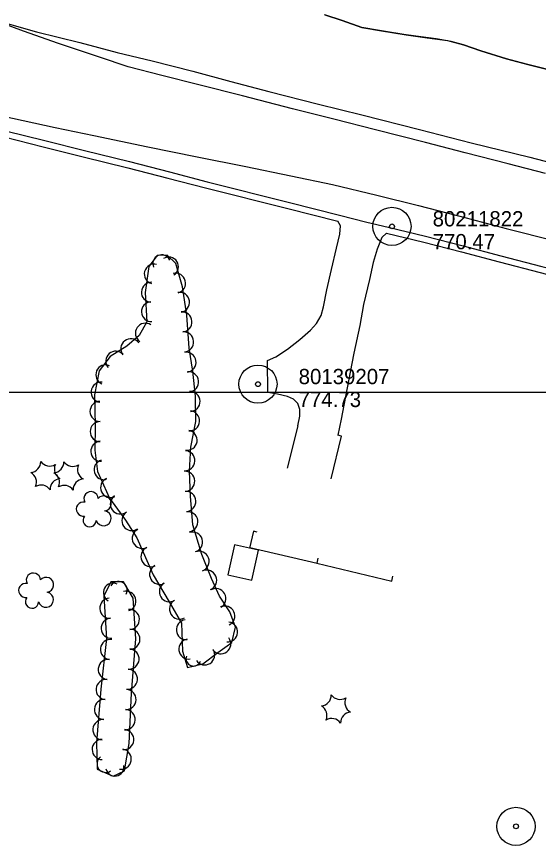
# Model space of a CAD drawing. Extents: x 591954 to 597000, y 198576 to 213500.
# Drawn here: x 595017.1 to 595222.2, y 204321.7 to 204647.7 of the extents above; entities that cross this region are included whole.
import ezdxf

# ---------------------------------------------------------------- set-up
doc = ezdxf.new("R2010")
doc.units = 0
for name, color, linetype in [('Level 10', 7, 'Continuous'), ('Level 11', 7, 'Continuous'), ('Level 12', 7, 'Continuous'), ('Level 17', 7, 'Continuous'), ('Level 18', 7, 'Continuous'), ('Level 19', 7, 'Continuous'), ('Level 6', 7, 'Continuous')]:
    doc.layers.add(name, color=color, linetype=linetype)

msp = doc.modelspace()

# ---------------------------------------------------------------- linework, layer by layer
at = {"layer": 'Level 10'}
for p, q in [((593000, 204500), (595500, 204500)), ((593500, 204500), (595500, 204500)), ((593500, 204500), (595500, 204500)), ((593500, 204500), (595500, 204500)), ((595000, 204500), (597000, 204500)), ((595000, 204500), (597000, 204500)), ((595000, 204500), (596500, 204500)), ((595000, 204500), (597000, 204500))]:
    msp.add_line(p, q, dxfattribs=at)
at = {"layer": 'Level 11'}
for points in [[(595224.97, 204586.04), (595210.37, 204589.77), (595193.43, 204594.13), (595177.84, 204598.22), (595158.18, 204603.13), (595141.83, 204607.31), (595125.55, 204611.39), (595105.88, 204616.5), (595088.67, 204620.86), (595074.21, 204624.5), (595060.97, 204627.89), (595049.61, 204631.71), (595033.55, 204637.19), (595019.8, 204641.98), (595005.86, 204647.05), (594993.12, 204651.53), (594979.84, 204656.41), (594967.44, 204660.94), (594954.87, 204665.35), (594939.32, 204670.85), (594927.26, 204674.99), (594916.36, 204678.96)], [(595005.86, 204647.05), (595024.86, 204641.67), (595041.9, 204637.49), (595056.66, 204633.54), (595070.43, 204630.34), (595086.32, 204626.2), (595101.34, 204622.24), (595116.19, 204618.3), (595135.83, 204613.2), (595152.76, 204609.04), (595175.42, 204603.27), (595195.76, 204598.05), (595218.8, 204592.36), (595237.83, 204587.45), (595258.62, 204582.22), (595263.39, 204580.93)], [(594920.11, 204626.29), (594929.43, 204625.11), (594944.34, 204622.44), (594960.83, 204619.1), (594979.1, 204615.35), (594995.08, 204612.07), (595011.29, 204608.67), (595032.2, 204604.07), (595047.39, 204600.89), (595068.67, 204596.46), (595088.03, 204592.56), (595107.19, 204588.7), (595124.89, 204585.02), (595141.21, 204581.6), (595158.77, 204577.41), (595175.05, 204573.35), (595193.87, 204568.54), (595209.58, 204564.41), (595228.78, 204559.47), (595248.11, 204554.48), (595258.57, 204551.71)], [(594939.05, 204621.53), (594953.65, 204617.93), (594967.96, 204614.26), (594982.89, 204610.4), (594998.31, 204606.54), (595012.74, 204602.83), (595028.16, 204598.92), (595043.8, 204595.01), (595061.43, 204590.65), (595077.18, 204586.59), (595091.96, 204582.77), (595124.37, 204574.62), (595143.98, 204569.66)], [(594938.45, 204619.1), (594953.04, 204615.5), (594967.34, 204611.84), (594982.27, 204607.98), (594997.69, 204604.12), (595012.13, 204600.41), (595027.55, 204596.49), (595043.2, 204592.58), (595060.81, 204588.23), (595076.55, 204584.17), (595091.35, 204580.35), (595123.76, 204572.2), (595143.37, 204567.23)], [(595143.98, 204569.66), (595154.79, 204566.89), (595163.1, 204564.93)], [(595163.1, 204564.93), (595177.83, 204561.34), (595192.63, 204557.54), (595207.41, 204553.66), (595223.56, 204549.46), (595237.63, 204545.85), (595252.82, 204541.69), (595256.74, 204540.65)], [(595162.51, 204562.51), (595177.22, 204558.91), (595192, 204555.12), (595206.78, 204551.24), (595222.93, 204547.04), (595236.99, 204543.43), (595252.17, 204539.28), (595256.33, 204538.18)]]:
    msp.add_lwpolyline(points, dxfattribs=at)
at = {"layer": 'Level 12'}
msp.add_lwpolyline([(595102.75, 204439.9), (595100.12, 204428.15), (595109.55, 204426.04), (595112.17, 204437.79), (595102.75, 204439.9)], dxfattribs=at)
at = {"layer": 'Level 17'}
for points in [[(595127.6, 204486.77), (595128.46, 204490.46), (595128.38, 204493.1), (595127.64, 204495.51), (595125.98, 204497.23), (595123.6, 204498.22), (595119.59, 204499.14), (595115.82, 204499.79), (595115.78, 204512.46), (595119.02, 204513.93), (595123.63, 204516.86), (595128.42, 204520.71), (595132.65, 204524.33), (595135.05, 204527.02), (595136.86, 204530.07), (595137.75, 204533.47), (595139.11, 204540.18), (595140.92, 204548.27), (595142.91, 204556.67), (595144.15, 204562.13), (595144.43, 204565.43), (595143.37, 204567.23)], [(595162.51, 204562.51), (595160.64, 204560.76), (595158.85, 204556.2), (595157.23, 204550.93), (595155.88, 204544.23), (595153.51, 204534.45), (595152.01, 204526.19), (595149.68, 204515.3), (595146.9, 204500.99), (595144.64, 204489.34), (595143.39, 204483.01)], [(595127.6, 204486.77), (595123.49, 204470.04)], [(595140.71, 204465.87), (595144.84, 204482.66)], [(595144.84, 204482.66), (595143.39, 204483.01)], [(595111.61, 204444.94), (595110.25, 204445.31), (595108.7, 204438.57)], [(595108.76, 204438.83), (595135.2, 204432.69), (595135.66, 204434.64)], [(595135.13, 204432.71), (595164.62, 204425.67), (595165.02, 204427.53)]]:
    msp.add_lwpolyline(points, dxfattribs=at)
at = {"layer": 'Level 18'}
for points in [[(595068.24, 204527.63), (595065.24, 204522.31), (595060.43, 204518.02), (595053.92, 204514.01), (595049.58, 204508.38), (595047.69, 204498.92), (595047.92, 204486.8), (595047.85, 204477.2), (595048.85, 204468.72), (595053.62, 204458.3), (595059.9, 204449.65), (595064.37, 204442.62), (595070.83, 204428.04), (595077.11, 204417.53), (595081.93, 204409.15), (595082.27, 204398.02), (595084.26, 204391.7), (595090.23, 204393.04), (595096.2, 204397.53), (595101.71, 204401.42), (595103.1, 204407.51), (595100.93, 204413.61), (595096.89, 204419.77), (595093.67, 204426.6), (595089.94, 204436.05), (595086.32, 204447.8), (595085.46, 204459), (595085.08, 204468.87), (595085.59, 204478.34), (595087.54, 204488.43), (595087.37, 204498.43), (595086.34, 204508.19), (595084.93, 204517.31), (595084.01, 204530.27), (595082.26, 204541.34), (595079.66, 204550.57), (595076.26, 204553.85), (595072.39, 204553.67), (595069.13, 204549.36), (595067.61, 204539.21), (595068.24, 204527.63)], [(595052.44, 204403.03), (595050.16, 204383.13), (595048.54, 204362.08), (595048.76, 204351.63), (595055.08, 204348.89), (595059.49, 204351.01), (595061.39, 204361.8), (595062.24, 204381.61), (595063.97, 204402.89), (595062.92, 204418.88), (595059.04, 204425.36), (595054.12, 204425.32), (595051.38, 204419.72), (595052.44, 204403.03)]]:
    msp.add_lwpolyline(points, dxfattribs=at)
for centre, radius, start, end in [((595074.1, 204550.52), 3.47, 24.1561, 204.1407), ((595076.89, 204549.31), 3.81, 302.4789, 122.4635), ((595071.16, 204546.5), 3.87, 75.2739, 255.2586), ((595079.58, 204542.83), 3.94, 284.1919, 104.1766), ((595070.07, 204539.25), 3.93, 87.0677, 267.0524), ((595081.13, 204535.29), 3.95, 278.981, 98.9657), ((595070.07, 204531.64), 3.91, 93.1346, 273.1193), ((595082.07, 204527.6), 3.95, 274.9497, 94.9344), ((595067.72, 204523.17), 3.91, 56.1429, 236.1275), ((595082.74, 204519.74), 3.95, 274.8539, 94.8385), ((595061.97, 204517.03), 3.93, 37.4892, 217.4739), ((595056, 204512.19), 3.89, 41.0424, 221.0271), ((595083.69, 204511.76), 3.95, 278.8283, 98.813), ((595052.08, 204506.84), 3.85, 66.9793, 246.9639), ((595084.7, 204504.03), 3.95, 276.0394, 96.0241), ((595050.27, 204499.94), 3.93, 82.8139, 262.7986), ((595085.26, 204496.3), 3.95, 272.2077, 92.1924), ((595049.88, 204492.39), 3.95, 91.0596, 271.0443), ((595085.09, 204488.7), 3.93, 265.0998, 85.0845), ((595049.95, 204484.45), 3.95, 89.9061, 269.8908), ((595084.12, 204481.06), 3.94, 260.5501, 80.5348), ((595050.19, 204476.7), 3.94, 93.7458, 273.7305), ((595083.23, 204473), 3.95, 266.9449, 86.9296), ((595022.28, 204472.65), 4.3, 275.2113, 0.9762), ((595030.09, 204475.2), 4.3, 215.2113, 300.9762), ((595031.35, 204472.52), 4.3, 275.2113, 0.9762), ((595039.17, 204475.08), 4.3, 215.2113, 300.9762), ((595051.41, 204469.43), 3.9, 105.6757, 285.6603), ((595036.21, 204469.71), 4.3, 155.2113, 240.9762), ((595045.29, 204469.58), 4.3, 155.2113, 240.9762), ((595020.58, 204464.61), 4.3, 335.2113, 60.9762), ((595034.52, 204461.67), 4.3, 95.2113, 180.9762), ((595029.66, 204464.48), 4.3, 335.2113, 60.9762), ((595054.04, 204462.43), 3.95, 115.186, 295.1707), ((595083.17, 204464.92), 3.95, 272.1774, 92.162), ((595026.7, 204459.12), 4.3, 35.2113, 120.9762), ((595035.77, 204458.99), 4.3, 35.2113, 120.9762), ((595043.59, 204461.54), 4.3, 95.2113, 180.9762), ((595046.33, 204458.05), 2.78, 1.3946, 209.1675), ((595083.58, 204456.97), 3.95, 273.8266, 93.8112), ((595043.33, 204453.98), 2.78, 78.0716, 279.0826), ((595051.37, 204456.2), 2.97, 278.4237, 139.6575), ((595057.84, 204456), 3.95, 126.0142, 305.9989), ((595051.26, 204450.34), 2.97, 196.0745, 79.0477), ((595084.45, 204448.98), 3.93, 278.4255, 98.4102), ((595045.79, 204449.58), 2.61, 140.7797, 358.7123), ((595062.4, 204449.44), 3.95, 123.5186, 303.5033), ((595066.48, 204442.43), 3.94, 116.9597, 296.9444), ((595086.25, 204441.02), 3.95, 287.1259, 107.1105), ((595069.91, 204435.21), 3.95, 113.9245, 293.9092), ((595088.83, 204433.43), 3.95, 290.5042, 110.4889), ((595073.31, 204428.27), 3.94, 118.2336, 298.2183), ((595023.66, 204426.02), 2.78, 1.3946, 209.1675), ((595028.7, 204424.16), 2.97, 278.4237, 139.6575), ((595091.81, 204426.01), 3.95, 293.3282, 113.3129), ((595020.66, 204421.95), 2.78, 78.0716, 279.0826), ((595054.88, 204421.16), 3.7, 61.8513, 241.836), ((595057.11, 204422.1), 3.45, 331.8137, 151.7983), ((595077.15, 204421.48), 3.95, 120.7711, 300.7558), ((595028.59, 204418.31), 2.97, 196.0745, 79.0477), ((595060.16, 204417.79), 3.87, 286.4754, 106.4601), ((595095.41, 204418.76), 3.94, 299.426, 119.4107), ((595023.12, 204417.55), 2.61, 140.7797, 358.7123), ((595053.76, 204414.98), 3.98, 93.6492, 273.6338), ((595081.16, 204414.64), 3.95, 119.9226, 299.9073), ((595061.38, 204410.55), 3.98, 273.7786, 93.7633), ((595098.96, 204411.92), 3.92, 295.2399, 115.2246), ((595054.24, 204407.08), 3.93, 93.6467, 273.6314), ((595083.76, 204406.53), 3.89, 95.9411, 275.9258), ((595100.12, 204405.62), 3.84, 264.5496, 84.5343), ((595061.61, 204402.78), 3.97, 269.4296, 89.4143), ((595054.04, 204398.75), 3.98, 83.4725, 263.4572), ((595084.75, 204398.89), 3.91, 98.6586, 278.6433), ((595097.38, 204400.94), 3.92, 216.3651, 36.3498), ((595061.25, 204395), 3.98, 265.3619, 85.3466), ((595091.05, 204396.56), 3.9, 212.7764, 32.7611), ((595053.14, 204390.86), 3.98, 83.4789, 263.4635), ((595086.62, 204395.18), 2.95, 160.4197, 340.4044), ((595060.6, 204387.07), 3.98, 265.3547, 85.3394), ((595052.31, 204382.99), 3.98, 84.5294, 264.5141), ((595060.08, 204379.07), 3.98, 267.1744, 87.1591), ((595051.63, 204375.1), 3.98, 85.6078, 265.5925), ((595136.51, 204380.83), 4.3, 275.2113, 0.9762), ((595144.32, 204383.38), 4.3, 215.2113, 300.9762), ((595150.44, 204377.89), 4.3, 155.2113, 240.9762), ((595059.71, 204371.12), 3.98, 267.5425, 87.5272), ((595134.81, 204372.79), 4.3, 335.2113, 60.9762), ((595140.93, 204367.3), 4.3, 35.2113, 120.9762), ((595148.75, 204369.85), 4.3, 95.2113, 180.9762), ((595051.02, 204367.18), 3.98, 85.6078, 265.5925), ((595059.2, 204363.28), 3.97, 264.9982, 84.9829), ((595050.74, 204359.41), 3.97, 90.2817, 270.2663), ((595058.19, 204355.59), 3.98, 260.0276, 80.0123), ((595052.05, 204353.72), 3.35, 125.5145, 305.4992), ((595055.71, 204352.48), 3.56, 190.8624, 10.8471)]:
    msp.add_arc(centre, radius, start, end, dxfattribs=at)
at = {"layer": 'Level 19'}
for p, q in [((595181.97, 204638.94), (595176.02, 204639.72)), ((595187.88, 204637.98), (595181.97, 204638.94))]:
    msp.add_line(p, q, dxfattribs=at)
for points in [[(595170.08, 204640.57), (595160.56, 204642.13), (595152.79, 204643.4), (595145.06, 204646.16), (595138.24, 204648.39), (595138.15, 204648.4)], [(595138.24, 204648.39), (595145.06, 204646.16), (595152.79, 204643.4), (595160.56, 204642.13), (595170.27, 204640.54), (595178.54, 204639.36), (595186.51, 204638.37), (595192.8, 204636.55), (595199.56, 204634.19), (595209.7, 204631.15), (595218.59, 204628.8), (595228.53, 204626.26)], [(595176.02, 204639.72), (595170.27, 204640.54), (595170.08, 204640.57)], [(595215.63, 204629.58), (595209.7, 204631.15), (595199.56, 204634.19), (595192.8, 204636.55), (595187.88, 204637.98)], [(595247.75, 204622.02), (595238.5, 204624.09), (595228.53, 204626.26), (595218.59, 204628.8), (595215.63, 204629.58)]]:
    msp.add_lwpolyline(points, dxfattribs=at)
at = {"layer": 'Level 6'}
for centre, radius in [((595164.65, 204565.18), 7.5), ((595164.65, 204565.18), 7.5), ((595164.65, 204565.18), 7.5), ((595164.65, 204565.18), 7.5), ((595164.65, 204565.18), 7.5), ((595164.65, 204565.18), 7.5), ((595164.65, 204565.18), 0.96), ((595164.65, 204565.18), 0.96), ((595164.65, 204565.18), 0.96), ((595164.65, 204565.18), 0.96), ((595164.65, 204565.18), 0.96), ((595164.65, 204565.18), 0.96), ((595111.97, 204503.12), 7.5), ((595111.97, 204503.12), 7.5), ((595111.97, 204503.12), 7.5), ((595111.97, 204503.12), 7.5), ((595111.97, 204503.12), 7.5), ((595111.97, 204503.12), 7.5), ((595111.97, 204503.12), 7.5), ((595111.97, 204503.12), 0.96), ((595111.97, 204503.12), 0.96), ((595111.97, 204503.12), 0.96), ((595111.97, 204503.12), 0.96), ((595111.97, 204503.12), 0.96), ((595111.97, 204503.12), 0.96), ((595111.97, 204503.12), 0.96), ((595213.42, 204329.15), 7.5), ((595213.42, 204329.15), 7.5), ((595213.42, 204329.15), 7.5), ((595213.42, 204329.15), 7.5), ((595213.42, 204329.15), 7.5), ((595213.42, 204329.15), 7.5), ((595213.42, 204329.15), 0.96), ((595213.42, 204329.15), 0.96), ((595213.42, 204329.15), 0.96), ((595213.42, 204329.15), 0.96), ((595213.42, 204329.15), 0.96), ((595213.42, 204329.15), 0.96)]:
    msp.add_circle(centre, radius, dxfattribs=at)

# ---------------------------------------------------------------- texts
for s, p in [('80211822', (595180.65, 204565.18)), ('80211822', (595180.65, 204565.18)), ('80211822', (595180.65, 204565.18)), ('80211822', (595180.65, 204565.18)), ('80211822', (595180.65, 204565.18)), ('80211822', (595180.65, 204565.18)), ('770.47', (595180.65, 204556.18)), ('770.47', (595180.65, 204556.18)), ('770.47', (595180.65, 204556.18)), ('770.47', (595180.65, 204556.18)), ('770.47', (595180.65, 204556.18)), ('770.47', (595180.65, 204556.18)), ('80139207', (595127.97, 204503.12)), ('80139207', (595127.97, 204503.12)), ('80139207', (595127.97, 204503.12)), ('80139207', (595127.97, 204503.12)), ('80139207', (595127.97, 204503.12)), ('80139207', (595127.97, 204503.12)), ('80139207', (595127.97, 204503.12)), ('774.73', (595127.97, 204494.12)), ('774.73', (595127.97, 204494.12)), ('774.73', (595127.97, 204494.12)), ('774.73', (595127.97, 204494.12)), ('774.73', (595127.97, 204494.12)), ('774.73', (595127.97, 204494.12)), ('774.73', (595127.97, 204494.12))]:
    msp.add_text(s, height=6, dxfattribs=at).set_placement(p)

doc.saveas('drawing.dxf')
